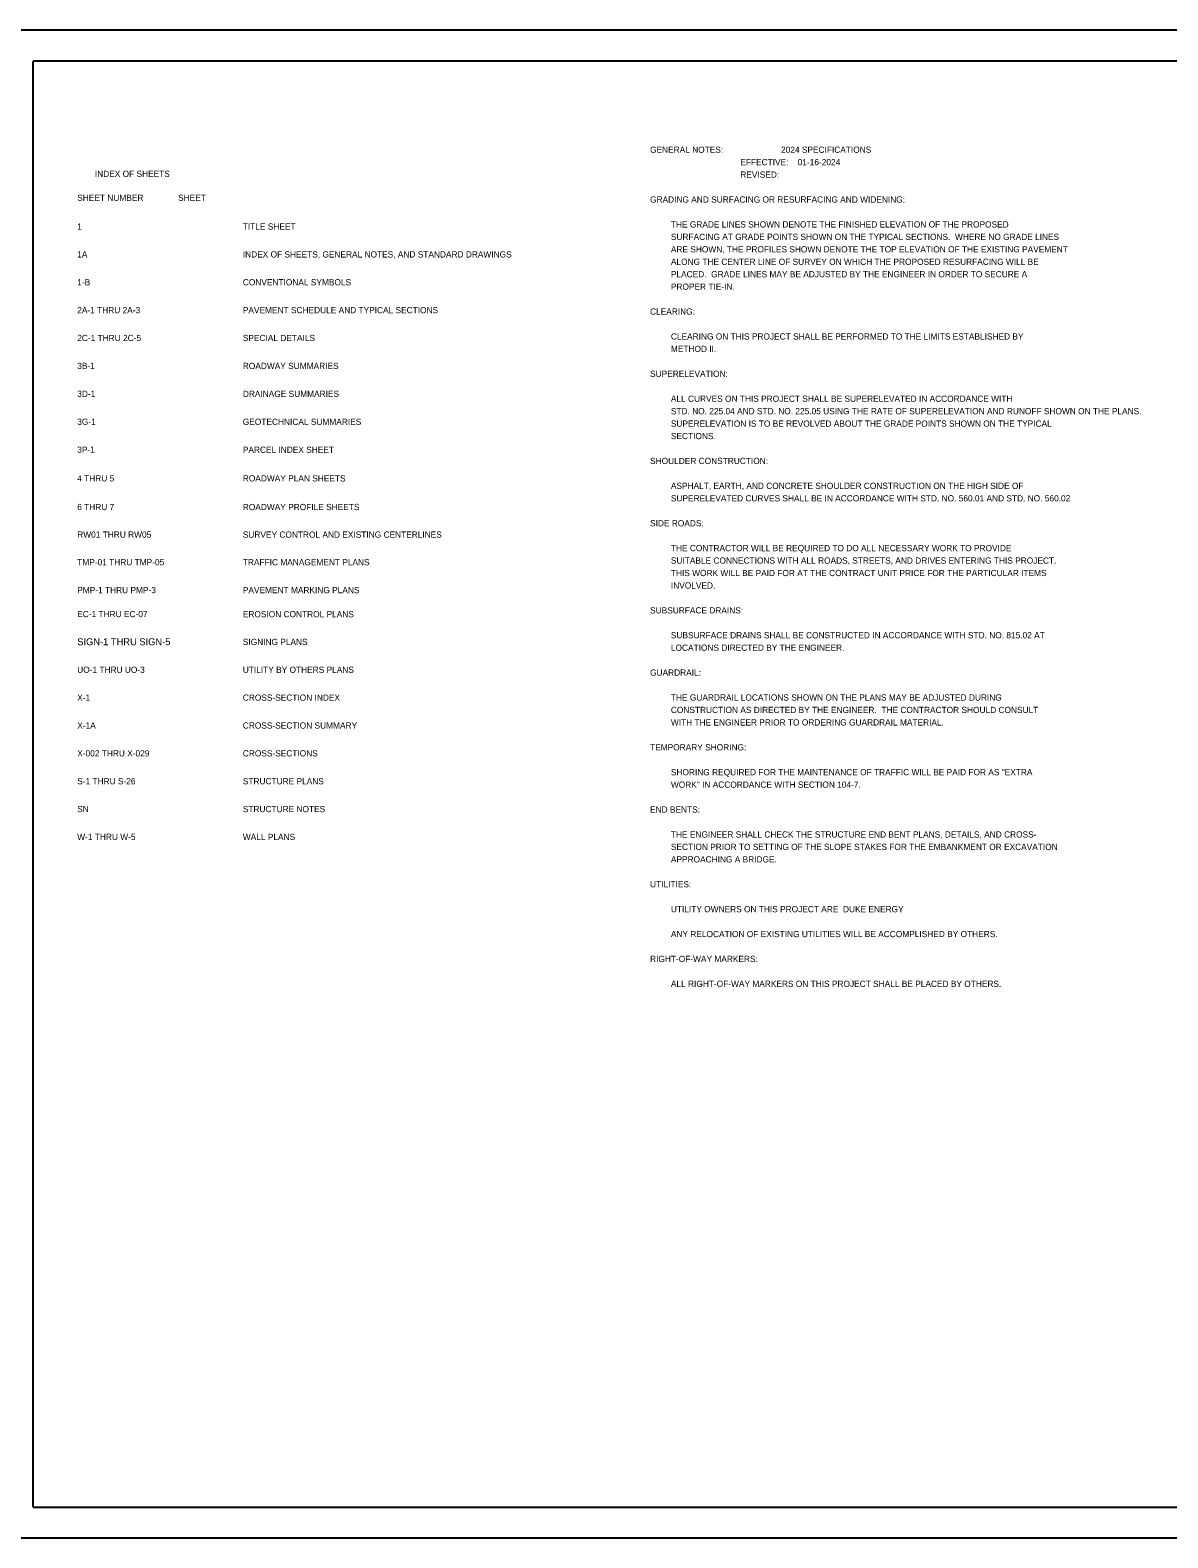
# Model space of a CAD drawing. Extents: x 1844369 to 1844800, y 671424 to 671721.
# Drawn here: x 1844443 to 1844512.4, y 671501.1 to 671593.1 of the extents above; entities that cross this region are included whole.
import ezdxf

# ---------------------------------------------------------------- set-up
doc = ezdxf.new("R2010")
doc.units = 0
for name, color, linetype in [('Sheet Data Text CELL', 7, 'Continuous'), ('Sheet_Clip_Boundary_CELL', 7, 'Continuous'), ('Sheet_Plan_CELL', 7, 'Continuous')]:
    doc.layers.add(name, color=color, linetype=linetype)

msp = doc.modelspace()

# ---------------------------------------------------------------- linework, layer by layer
at = {"layer": 'Sheet_Clip_Boundary_CELL'}
msp.add_lwpolyline([(1844581.788, 671593.106), (1844440.123, 671593.106), (1844440.123, 671501.068), (1844581.788, 671501.068)], close=True, dxfattribs=at)
at = {"layer": 'Sheet_Plan_CELL'}
for p, q in [((1844443.144, 671502.951), (1844443.146, 671591.223)), ((1844579.905, 671591.223), (1844443.146, 671591.223)), ((1844443.144, 671502.951), (1844579.903, 671502.951))]:
    msp.add_line(p, q, dxfattribs=at)

# ---------------------------------------------------------------- texts
at = {"layer": 'Sheet Data Text CELL'}
for s, height, p in [('GENERAL NOTES:                         2024 SPECIFICATIONS', 0.38, (1844480.779, 671585.618)), ('                                       EFFECTIVE:    01-16-2024', 0.38, (1844480.779, 671584.858)), ('                        INDEX OF SHEETS ', 0.38, (1844443.513, 671584.146)), ('                                       REVISED:      ', 0.38, (1844480.779, 671584.098)), ('SHEET NUMBER               SHEET   ', 0.38, (1844445.826, 671582.683)), ('GRADING AND SURFACING OR RESURFACING AND WIDENING:  ', 0.38, (1844480.779, 671582.578)), ('         THE GRADE LINES SHOWN DENOTE THE FINISHED ELEVATION OF THE PROPOSED ', 0.38, (1844480.779, 671581.058)), ('1', 0.38, (1844445.826, 671580.928)), ('TITLE SHEET', 0.38, (1844455.93, 671580.928)), ('         SURFACING AT GRADE POINTS SHOWN ON THE TYPICAL SECTIONS.  WHERE NO GRADE LINES ', 0.38, (1844480.779, 671580.298)), ('1A', 0.38, (1844445.826, 671579.227)), ('INDEX OF SHEETS, GENERAL NOTES, AND STANDARD DRAWINGS', 0.38, (1844455.93, 671579.227)), ('         ARE SHOWN, THE PROFILES SHOWN DENOTE THE TOP ELEVATION OF THE EXISTING PAVEMENT ', 0.38, (1844480.779, 671579.538)), ('         ALONG THE CENTER LINE OF SURVEY ON WHICH THE PROPOSED RESURFACING WILL BE ', 0.38, (1844480.779, 671578.778)), ('1-B', 0.38, (1844445.826, 671577.526)), ('CONVENTIONAL SYMBOLS ', 0.38, (1844455.93, 671577.526)), ('         PLACED.  GRADE LINES MAY BE ADJUSTED BY THE ENGINEER IN ORDER TO SECURE A ', 0.38, (1844480.779, 671578.018)), ('         PROPER TIE-IN.  ', 0.38, (1844480.779, 671577.258)), ('2A-1 THRU 2A-3', 0.38, (1844445.826, 671575.826)), ('PAVEMENT SCHEDULE AND TYPICAL SECTIONS', 0.38, (1844455.93, 671575.826)), ('CLEARING:  ', 0.38, (1844480.779, 671575.738)), ('2C-1 THRU 2C-5', 0.38, (1844445.826, 671574.125)), ('SPECIAL DETAILS', 0.38, (1844455.93, 671574.125)), ('         CLEARING ON THIS PROJECT SHALL BE PERFORMED TO THE LIMITS ESTABLISHED BY ', 0.38, (1844480.779, 671574.218)), ('         METHOD II.', 0.38, (1844480.779, 671573.458)), ('3B-1', 0.38, (1844445.826, 671572.424)), ('ROADWAY SUMMARIES', 0.38, (1844455.93, 671572.419)), ('SUPERELEVATION:  ', 0.38, (1844480.779, 671571.938)), ('3D-1', 0.38, (1844445.826, 671570.718)), ('DRAINAGE SUMMARIES', 0.38, (1844455.93, 671570.713)), ('         ALL CURVES ON THIS PROJECT SHALL BE SUPERELEVATED IN ACCORDANCE WITH', 0.38, (1844480.779, 671570.418)), ('         STD. NO. 225.04 AND STD. NO. 225.05 USING THE RATE OF SUPERELEVATION AND RUNOFF SHOWN ON THE PLANS.', 0.38, (1844480.779, 671569.658)), ('3G-1', 0.38, (1844445.826, 671569.012)), ('GEOTECHNICAL SUMMARIES', 0.38, (1844455.93, 671569.007)), ('         SUPERELEVATION IS TO BE REVOLVED ABOUT THE GRADE POINTS SHOWN ON THE TYPICAL ', 0.38, (1844480.779, 671568.898)), ('3P-1', 0.38, (1844445.826, 671567.306)), ('PARCEL INDEX SHEET', 0.38, (1844455.93, 671567.301)), ('         SECTIONS.  ', 0.38, (1844480.779, 671568.138)), ('SHOULDER CONSTRUCTION:  ', 0.38, (1844480.779, 671566.618)), ('4 THRU 5', 0.38, (1844445.826, 671565.556)), ('ROADWAY PLAN SHEETS', 0.38, (1844455.93, 671565.556)), ('         ASPHALT, EARTH, AND CONCRETE SHOULDER CONSTRUCTION ON THE HIGH SIDE OF', 0.38, (1844480.779, 671565.098)), ('6 THRU 7', 0.38, (1844445.826, 671563.807)), ('ROADWAY PROFILE SHEETS', 0.38, (1844455.93, 671563.807)), ('         SUPERELEVATED CURVES SHALL BE IN ACCORDANCE WITH STD. NO. 560.01 AND STD. NO. 560.02', 0.38, (1844480.779, 671564.338)), ('SIDE ROADS:  ', 0.38, (1844480.779, 671562.818)), ('RW01 THRU RW05', 0.38, (1844445.826, 671562.122)), ('         THE CONTRACTOR WILL BE REQUIRED TO DO ALL NECESSARY WORK TO PROVIDE ', 0.38, (1844480.779, 671561.298)), ('         SUITABLE CONNECTIONS WITH ALL ROADS, STREETS, AND DRIVES ENTERING THIS PROJECT.  ', 0.38, (1844480.779, 671560.538)), ('         THIS WORK WILL BE PAID FOR AT THE CONTRACT UNIT PRICE FOR THE PARTICULAR ITEMS ', 0.38, (1844480.779, 671559.778)), ('         INVOLVED.  ', 0.38, (1844480.779, 671559.018)), ('EC-1 THRU EC-07', 0.38, (1844445.826, 671557.272)), ('SUBSURFACE DRAINS:', 0.38, (1844480.779, 671557.498)), ('SIGN-1 THRU SIGN-5', 0.42516, (1844445.826, 671555.557)), ('         SUBSURFACE DRAINS SHALL BE CONSTRUCTED IN ACCORDANCE WITH STD. NO. 815.02 AT ', 0.38, (1844480.779, 671555.978)), ('         LOCATIONS DIRECTED BY THE ENGINEER.  ', 0.38, (1844480.779, 671555.218)), ('UO-1 THRU UO-3', 0.38, (1844445.826, 671553.871)), ('UTILITY BY OTHERS PLANS', 0.38, (1844455.93, 671553.871)), ('GUARDRAIL:  ', 0.38, (1844480.779, 671553.698)), ('X-1', 0.38, (1844445.826, 671552.17)), ('CROSS-SECTION INDEX', 0.38, (1844455.93, 671552.17)), ('         THE GUARDRAIL LOCATIONS SHOWN ON THE PLANS MAY BE ADJUSTED DURING ', 0.38, (1844480.779, 671552.178)), ('         WITH THE ENGINEER PRIOR TO ORDERING GUARDRAIL MATERIAL.', 0.38, (1844480.779, 671550.658)), ('         CONSTRUCTION AS DIRECTED BY THE ENGINEER.  THE CONTRACTOR SHOULD CONSULT', 0.38, (1844480.779, 671551.418)), ('X-1A', 0.38, (1844445.826, 671550.469)), ('CROSS-SECTION SUMMARY', 0.38, (1844455.93, 671550.469)), ('TEMPORARY SHORING:  ', 0.38, (1844480.779, 671549.138)), ('X-002 THRU X-029', 0.38, (1844445.826, 671548.769)), ('CROSS-SECTIONS', 0.38, (1844455.93, 671548.769)), ('S-1 THRU S-26', 0.38, (1844445.826, 671547.068)), ('STRUCTURE PLANS', 0.38, (1844455.93, 671547.068)), ('         SHORING REQUIRED FOR THE MAINTENANCE OF TRAFFIC WILL BE PAID FOR AS "EXTRA ', 0.38, (1844480.779, 671547.618)), ('         WORK" IN ACCORDANCE WITH SECTION 104-7.  ', 0.38, (1844480.779, 671546.858)), ('SN', 0.38, (1844445.826, 671545.368)), ('STRUCTURE NOTES', 0.38, (1844455.93, 671545.368)), ('END BENTS:  ', 0.38, (1844480.779, 671545.338)), ('W-1 THRU W-5', 0.38, (1844445.826, 671543.667)), ('WALL PLANS', 0.38, (1844455.93, 671543.667)), ('         THE ENGINEER SHALL CHECK THE STRUCTURE END BENT PLANS, DETAILS, AND CROSS-', 0.38, (1844480.779, 671543.818)), ('         SECTION PRIOR TO SETTING OF THE SLOPE STAKES FOR THE EMBANKMENT OR EXCAVATION ', 0.38, (1844480.779, 671543.058)), ('         APPROACHING A BRIDGE.  ', 0.38, (1844480.779, 671542.298)), ('UTILITIES:  ', 0.38, (1844480.779, 671540.778)), ('         UTILITY OWNERS ON THIS PROJECT ARE  DUKE ENERGY', 0.38, (1844480.779, 671539.258)), ('         ANY RELOCATION OF EXISTING UTILITIES WILL BE ACCOMPLISHED BY OTHERS.  ', 0.38, (1844480.779, 671537.738)), ('RIGHT-OF-WAY MARKERS:  ', 0.38, (1844480.779, 671536.218)), ('         ALL RIGHT-OF-WAY MARKERS ON THIS PROJECT SHALL BE PLACED BY OTHERS.  ', 0.38, (1844480.779, 671534.698))]:
    msp.add_text(s, height=height, dxfattribs=at).set_placement(p)
for s, p in [('SURVEY CONTROL AND EXISTING CENTERLINES', (1844455.93, 671562.122)), ('TMP-01 THRU TMP-05', (1844445.826, 671560.437)), ('TRAFFIC MANAGEMENT PLANS', (1844455.93, 671560.437)), ('PMP-1 THRU PMP-3', (1844445.826, 671558.736)), ('PAVEMENT MARKING PLANS', (1844455.93, 671558.736)), ('EROSION CONTROL PLANS', (1844455.93, 671557.264)), ('SIGNING PLANS', (1844455.93, 671555.571))]:
    msp.add_text(s, height=0.38, rotation=360, dxfattribs=at).set_placement(p)

doc.saveas('drawing.dxf')
